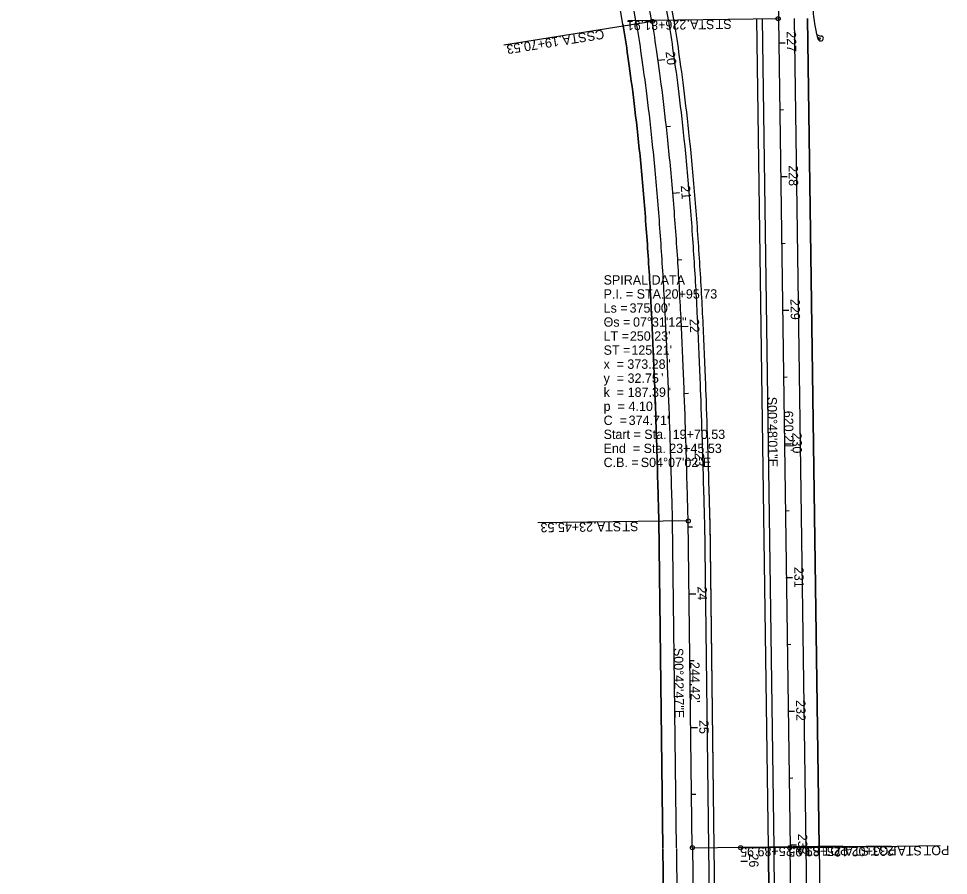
# Model space of a CAD drawing. Extents: x 76539 to 88870, y 518807 to 527554.
# Drawn here: x 87183 to 87878, y 521202 to 521842 of the extents above; entities that cross this region are included whole.
import ezdxf

# ---------------------------------------------------------------- set-up
doc = ezdxf.new("R2010")
doc.units = 0
for name, color, linetype in [('Default', 7, 'Continuous'), ('GE_P_Alignment_100_Bearings', 7, 'Continuous'), ('GE_P_Alignment_100_Cardinal_Points', 7, 'Continuous'), ('GE_P_Alignment_100_Curve_Data', 7, 'Continuous'), ('GE_P_Alignment_100_Distances', 7, 'Continuous'), ('GE_P_Alignment_100_Stations', 7, 'Continuous'), ('PM_P_Edge_Line', 7, 'Continuous'), ('PM_P_Lane_Line', 7, 'Continuous'), ('PV_P_Shoulder', 7, 'Continuous'), ('RD_P_GR_Lt', 7, 'Continuous'), ('RD_P_GR_Rt', 7, 'Continuous'), ('XS_P_Pavt_Surface', 7, 'Continuous')]:
    doc.layers.add(name, color=color, linetype=linetype)

msp = doc.modelspace()

# ---------------------------------------------------------------- linework, layer by layer
at = {"layer": 'Default'}
msp.add_open_spline([(87727.6, 522191.42), (87728.86, 522179.82), (87731.39, 522156.63), (87735.11, 522121.82), (87738.65, 522087), (87741.93, 522052.15), (87744.88, 522017.27), (87747.39, 521982.36), (87749.41, 521947.41), (87750.8, 521912.43), (87751.57, 521877.43), (87751.42, 521854.09), (87751.35, 521842.42)], degree=3, dxfattribs=at)
at = {"layer": 'GE_P_Alignment_100_Cardinal_Points'}
for p, q in [((87656.91, 521840.42), (87545.83, 521822.57)), ((87751.01, 521842.42), (87638.53, 521840.85)), ((87683.81, 521466.67), (87571.32, 521465.27)), ((87686.85, 521222.27), (87799.35, 521223.67)), ((87722.91, 521222.27), (87835.4, 521223.72)), ((87759.68, 521222.27), (87872.17, 521223.84))]:
    msp.add_line(p, q, dxfattribs=at)
for centre in [(87656.91, 521840.42), (87751.01, 521842.42), (87683.81, 521466.67), (87686.85, 521222.27), (87722.91, 521222.27), (87759.68, 521222.27)]:
    msp.add_circle(centre, 1.5, dxfattribs=at)
at = {"layer": 'GE_P_Alignment_100_Stations'}
for p, q in [((87751.27, 521824.33), (87756.27, 521824.4)), ((87661.29, 521811.27), (87666.24, 521811.97)), ((87751.97, 521774.34), (87754.97, 521774.38)), ((87667.49, 521761.66), (87670.47, 521761.99)), ((87752.66, 521724.34), (87757.66, 521724.41)), ((87672.31, 521711.9), (87677.29, 521712.32)), ((87753.36, 521674.35), (87756.36, 521674.39)), ((87675.99, 521662.03), (87678.99, 521662.22)), ((87754.06, 521624.35), (87759.06, 521624.42)), ((87678.76, 521612.11), (87683.76, 521612.35)), ((87754.76, 521574.36), (87757.76, 521574.4)), ((87680.86, 521562.15), (87683.85, 521562.26)), ((87755.46, 521524.36), (87760.46, 521524.43)), ((87682.5, 521512.18), (87687.5, 521512.33)), ((87756.16, 521474.37), (87759.16, 521474.41)), ((87683.87, 521462.2), (87686.87, 521462.24)), ((87756.85, 521424.37), (87761.85, 521424.44)), ((87684.49, 521412.2), (87689.49, 521412.27)), ((87757.55, 521374.38), (87760.55, 521374.42)), ((87685.11, 521362.21), (87688.11, 521362.25)), ((87758.25, 521324.38), (87763.25, 521324.45)), ((87685.73, 521312.21), (87690.73, 521312.27)), ((87758.95, 521274.39), (87761.95, 521274.43)), ((87686.36, 521262.22), (87689.36, 521262.25)), ((87759.65, 521224.39), (87764.65, 521224.46)), ((87723.04, 521212.22), (87728.04, 521212.29))]:
    msp.add_line(p, q, dxfattribs=at)
at = {"layer": 'PM_P_Edge_Line'}
for p, q in [((87739.02, 521842.59), (87739.01, 521842.36)), ((87739.01, 521842.36), (87747.68, 521222.11)), ((87763.01, 521842.48), (87771.68, 521222.44)), ((87763.01, 521842.48), (87771.68, 521222.44)), ((87671.81, 521467.13), (87674.85, 521222.12)), ((87695.82, 521466.23), (87698.85, 521222.42)), ((87674.86, 521221.66), (87677.11, 521046.05)), ((87698.86, 521221.97), (87701.12, 521045.87)), ((87747.67, 521222.59), (87749.94, 521045.5)), ((87771.67, 521222.9), (87773.95, 521045.31))]:
    msp.add_line(p, q, dxfattribs=at)
for radius, start in [(1440.6, 9.83522), (1416.6, 9.91089)]:
    msp.add_arc((86249.47, 521595.47), radius, start, 48.42092, dxfattribs=at)
for points in [[(87668.88, 521841.55), (87670.12, 521833.8), (87672.48, 521818.29), (87676.71, 521787.19), (87681.17, 521748.22), (87685.37, 521701.33), (87688.62, 521654.37), (87691.09, 521607.36), (87692.99, 521560.33), (87694.25, 521521.12), (87695.17, 521489.75), (87695.61, 521474.07), (87695.83, 521466.23)], [(87644.94, 521839.29), (87646.17, 521831.61), (87648.53, 521816.23), (87652.75, 521785.4), (87657.2, 521746.75), (87661.39, 521700.26), (87664.62, 521653.69), (87667.09, 521607.08), (87668.98, 521560.44), (87670.23, 521521.56), (87671.14, 521490.46), (87671.58, 521474.9), (87671.8, 521467.13)]]:
    msp.add_open_spline(points, degree=3, dxfattribs=at)
at = {"layer": 'PM_P_Lane_Line'}
for p, q in [((87751.35, 521842.42), (87760.01, 521222.28)), ((87683.48, 521466.69), (87686.52, 521222.27)), ((87686.86, 521221.81), (87689.11, 521045.96)), ((87759.67, 521222.74), (87761.95, 521045.4))]:
    msp.add_line(p, q, dxfattribs=at)
msp.add_arc((86249.47, 521595.47), 1428.27, 9.87385, 48.42092, dxfattribs=at)
msp.add_open_spline([(87656.58, 521840.39), (87657.82, 521832.68), (87660.17, 521817.23), (87664.4, 521786.27), (87668.85, 521747.46), (87673.05, 521700.78), (87676.29, 521654.02), (87678.76, 521607.22), (87680.65, 521560.38), (87681.91, 521521.35), (87682.82, 521490.11), (87683.26, 521474.5), (87683.48, 521466.69)], degree=3, dxfattribs=at)
at = {"layer": 'PV_P_Shoulder'}
for p, q in [((87735.01, 521842.35), (87735.02, 521842.61)), ((87743.67, 521222.54), (87735.01, 521842.35)), ((87781.67, 521223.03), (87773.02, 521842.55)), ((87661.8, 521467.5), (87664.86, 521222)), ((87699.82, 521466.08), (87702.85, 521222.47)), ((87664.86, 521221.53), (87667.11, 521046.13)), ((87702.86, 521222.02), (87705.12, 521045.84)), ((87743.67, 521222.54), (87745.94, 521045.53)), ((87781.67, 521223.03), (87783.95, 521045.23))]:
    msp.add_line(p, q, dxfattribs=at)
for radius, start in [(1444.6, 9.8228), (1406.6, 9.94301)]:
    msp.add_arc((86249.47, 521595.47), radius, start, 48.42092, dxfattribs=at)
for points in [[(87672.87, 521841.92), (87674.11, 521834.16), (87676.47, 521818.63), (87680.7, 521787.49), (87685.16, 521748.46), (87689.37, 521701.51), (87692.61, 521654.48), (87695.09, 521607.41), (87696.99, 521560.31), (87698.26, 521521.05), (87699.17, 521489.64), (87699.61, 521473.93), (87699.84, 521466.08)], [(87634.96, 521838.35), (87636.2, 521830.7), (87638.55, 521815.37), (87642.77, 521784.65), (87647.21, 521746.14), (87651.4, 521699.82), (87654.63, 521653.41), (87657.09, 521606.96), (87658.97, 521560.49), (87660.22, 521521.75), (87661.13, 521490.75), (87661.56, 521475.25), (87661.78, 521467.5)]]:
    msp.add_open_spline(points, degree=3, dxfattribs=at)
at = {"layer": 'RD_P_GR_Lt'}
msp.add_arc((87877.48, 521854.44), 100.51, 181.62988, 193.53487, dxfattribs=at)
at = {"layer": 'RD_P_GR_Rt'}
msp.add_circle((87781.6, 521827.51), 0.79, dxfattribs=at)
for centre, major_axis, start_param, end_param in [((87783.7, 521834.79), (-5.69, 0.24), 0.847713, 1.513095), ((87790.29, 521831.21), (-10.36, 0.44), 0.162527, 0.519896), ((87782.87, 521827.61), (1.99, -0.08), 3.668244, 7.768795)]:
    msp.add_ellipse(centre, major_axis=major_axis, ratio=0.944544, start_param=start_param, end_param=end_param, dxfattribs=at)
at = {"layer": 'XS_P_Pavt_Surface'}
for p, q in [((87743.67, 521222.54), (87735.01, 521842.35)), ((87773.02, 521842.55), (87781.67, 521223.03)), ((87664.86, 521222), (87661.8, 521467.5)), ((87699.81, 521467), (87702.85, 521222.47)), ((87667.11, 521046.13), (87664.86, 521221.53)), ((87702.86, 521222.02), (87705.12, 521045.84)), ((87745.94, 521045.53), (87743.67, 521222.54)), ((87781.67, 521223.03), (87783.95, 521045.23))]:
    msp.add_line(p, q, dxfattribs=at)
for centre, radius, start, end in [((86249.46, 521595.47), 1444.6, 9.8228, 48.42092), ((86249.77, 521595.64), 1406.27, 9.93828, 48.41618)]:
    msp.add_arc(centre, radius, start, end, dxfattribs=at)
for points in [[(87672.87, 521841.92), (87674.11, 521834.16), (87676.47, 521818.63), (87680.7, 521787.49), (87685.16, 521748.46), (87689.37, 521701.51), (87692.61, 521654.48), (87695.09, 521607.41), (87696.99, 521560.31), (87698.26, 521521.05), (87699.16, 521489.94), (87699.6, 521474.54), (87699.81, 521467)], [(87661.78, 521467.5), (87661.56, 521475.25), (87661.13, 521490.75), (87660.22, 521521.75), (87658.97, 521560.49), (87657.09, 521606.96), (87654.63, 521653.41), (87651.4, 521699.81), (87647.21, 521746.14), (87642.77, 521784.65), (87638.55, 521815.37), (87636.2, 521830.7), (87634.96, 521838.35)]]:
    msp.add_open_spline(points, degree=3, dxfattribs=at)

# ---------------------------------------------------------------- texts
at = {"layer": 'GE_P_Alignment_100_Bearings'}
for s, rotation, p in [('S00°48\'01"E', 270.80041, (87742.97, 521559.52)), ('S00°42\'47"E', 270.71294, (87672.99, 521371.67))]:
    msp.add_text(s, height=7, rotation=rotation, dxfattribs=at).set_placement(p)
at = {"layer": 'GE_P_Alignment_100_Cardinal_Points'}
for s, rotation, p in [('226+81.91', 180.80041, (87682.25, 521841.36)), (' STA. ', 180.80041, (87705.88, 521841.69)), ('ST', 180.80041, (87716.17, 521841.83)), ('CS', 189.13092, (87620.29, 521834.43)), ('19+70.53', 189.13092, (87586.34, 521828.97)), (' STA. ', 189.13092, (87609.67, 521832.72)), ('23+45.53', 180.71294, (87612.56, 521465.68)), (' STA. ', 180.71294, (87636.19, 521465.98)), ('ST', 180.71294, (87646.48, 521466.1)), ('25+89.95', 180.71294, (87761.82, 521223.1)), ('25+89.95', 180.73436, (87797.88, 521223.13)), (' STA. ', 180.71294, (87785.44, 521223.4)), ('POT', 180.71294, (87803.45, 521223.62)), ('233+02.12', 180.80041, (87837.37, 521223.25)), (' STA. ', 180.73436, (87821.5, 521223.43)), ('POT', 180.73436, (87839.5, 521223.66)), (' STA. ', 180.80041, (87861, 521223.58)), ('POT', 180.80041, (87879, 521223.84))]:
    msp.add_text(s, height=7, rotation=rotation, dxfattribs=at).set_placement(p)
at = {"layer": 'GE_P_Alignment_100_Curve_Data'}
for s, p in [('SPIRAL DATA', (87620.45, 521643.5)), ('P.I. = STA. ', (87620.45, 521633)), ('20+95.73', (87666.12, 521633)), ('Ls = ', (87620.45, 521622.5)), ("375.00'", (87639.86, 521622.5)), ('Θs = ', (87620.45, 521612)), ('07°31\'12"', (87642.46, 521612)), ('LT = ', (87620.45, 521601.5)), ("250.23'", (87640.09, 521601.5)), ('ST = ', (87620.45, 521591)), ("125.21'", (87641.22, 521591)), ('x  = ', (87620.45, 521580.5)), ('373.28', (87638.2, 521580.5)), ("'", (87668.92, 521580.5)), ('y  = ', (87620.45, 521570)), ('32.75', (87638.36, 521570)), ("'", (87663.49, 521570)), ('k  = ', (87620.45, 521559.5)), ('187.39', (87638.44, 521559.5)), ("'", (87669.16, 521559.5)), ('p  = ', (87620.45, 521549)), ('4.10', (87639.09, 521549)), ("'", (87658.64, 521549)), ('C  = ', (87620.45, 521538.5)), ("374.71'", (87639.19, 521538.5)), ('Start = Sta. ', (87620.45, 521528)), ('19+70.53', (87672.09, 521528)), ('End  = Sta. ', (87620.45, 521517.5)), ('23+45.53', (87669.54, 521517.5)), ('C.B. = ', (87620.45, 521507)), ('S04°07\'02"E', (87648.27, 521507))]:
    msp.add_text(s, height=7, dxfattribs=at).set_placement(p)
at = {"layer": 'GE_P_Alignment_100_Distances'}
for s, rotation, p in [("620.21'", 270.80041, (87755.22, 521549.05)), ("244.42'", 270.71294, (87685.17, 521361.17))]:
    msp.add_text(s, height=7, rotation=rotation, dxfattribs=at).set_placement(p)
at = {"layer": 'GE_P_Alignment_100_Stations'}
for s, rotation, p in [('227', 270.80041, (87757.4, 521832.96)), ('20', 277.99529, (87666.71, 521817.66)), ('228', 270.80041, (87758.8, 521732.77)), ('21', 274.83464, (87678.11, 521717.49)), ('229', 270.80041, (87760.19, 521632.74)), ('22', 272.74349, (87684.75, 521617.81)), ('230', 270.80041, (87761.59, 521532.82)), ('23', 271.72184, (87688.59, 521517.75)), ('231', 270.80041, (87762.99, 521432.34)), ('24', 270.71294, (87690.67, 521417.67)), ('232', 270.80041, (87764.39, 521332.67)), ('25', 270.71294, (87691.92, 521317.76)), ('233', 270.80041, (87765.78, 521232.66)), ('26', 270.73436, (87729.22, 521217.91))]:
    msp.add_text(s, height=7, rotation=rotation, dxfattribs=at).set_placement(p)

doc.saveas('drawing.dxf')
